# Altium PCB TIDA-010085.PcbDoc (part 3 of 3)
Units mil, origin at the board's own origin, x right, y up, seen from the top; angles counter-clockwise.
Board outline 1968.5 x 2559.06 mil, 4 copper layers (Top Layer, Signal Layer 1, Signal Layer 2, Bottom Layer), stack 5.6 mil thick; 254 components, 133 nets, 771 pads, 156 vias.
Unrouted connection lines stored in the file: 2.
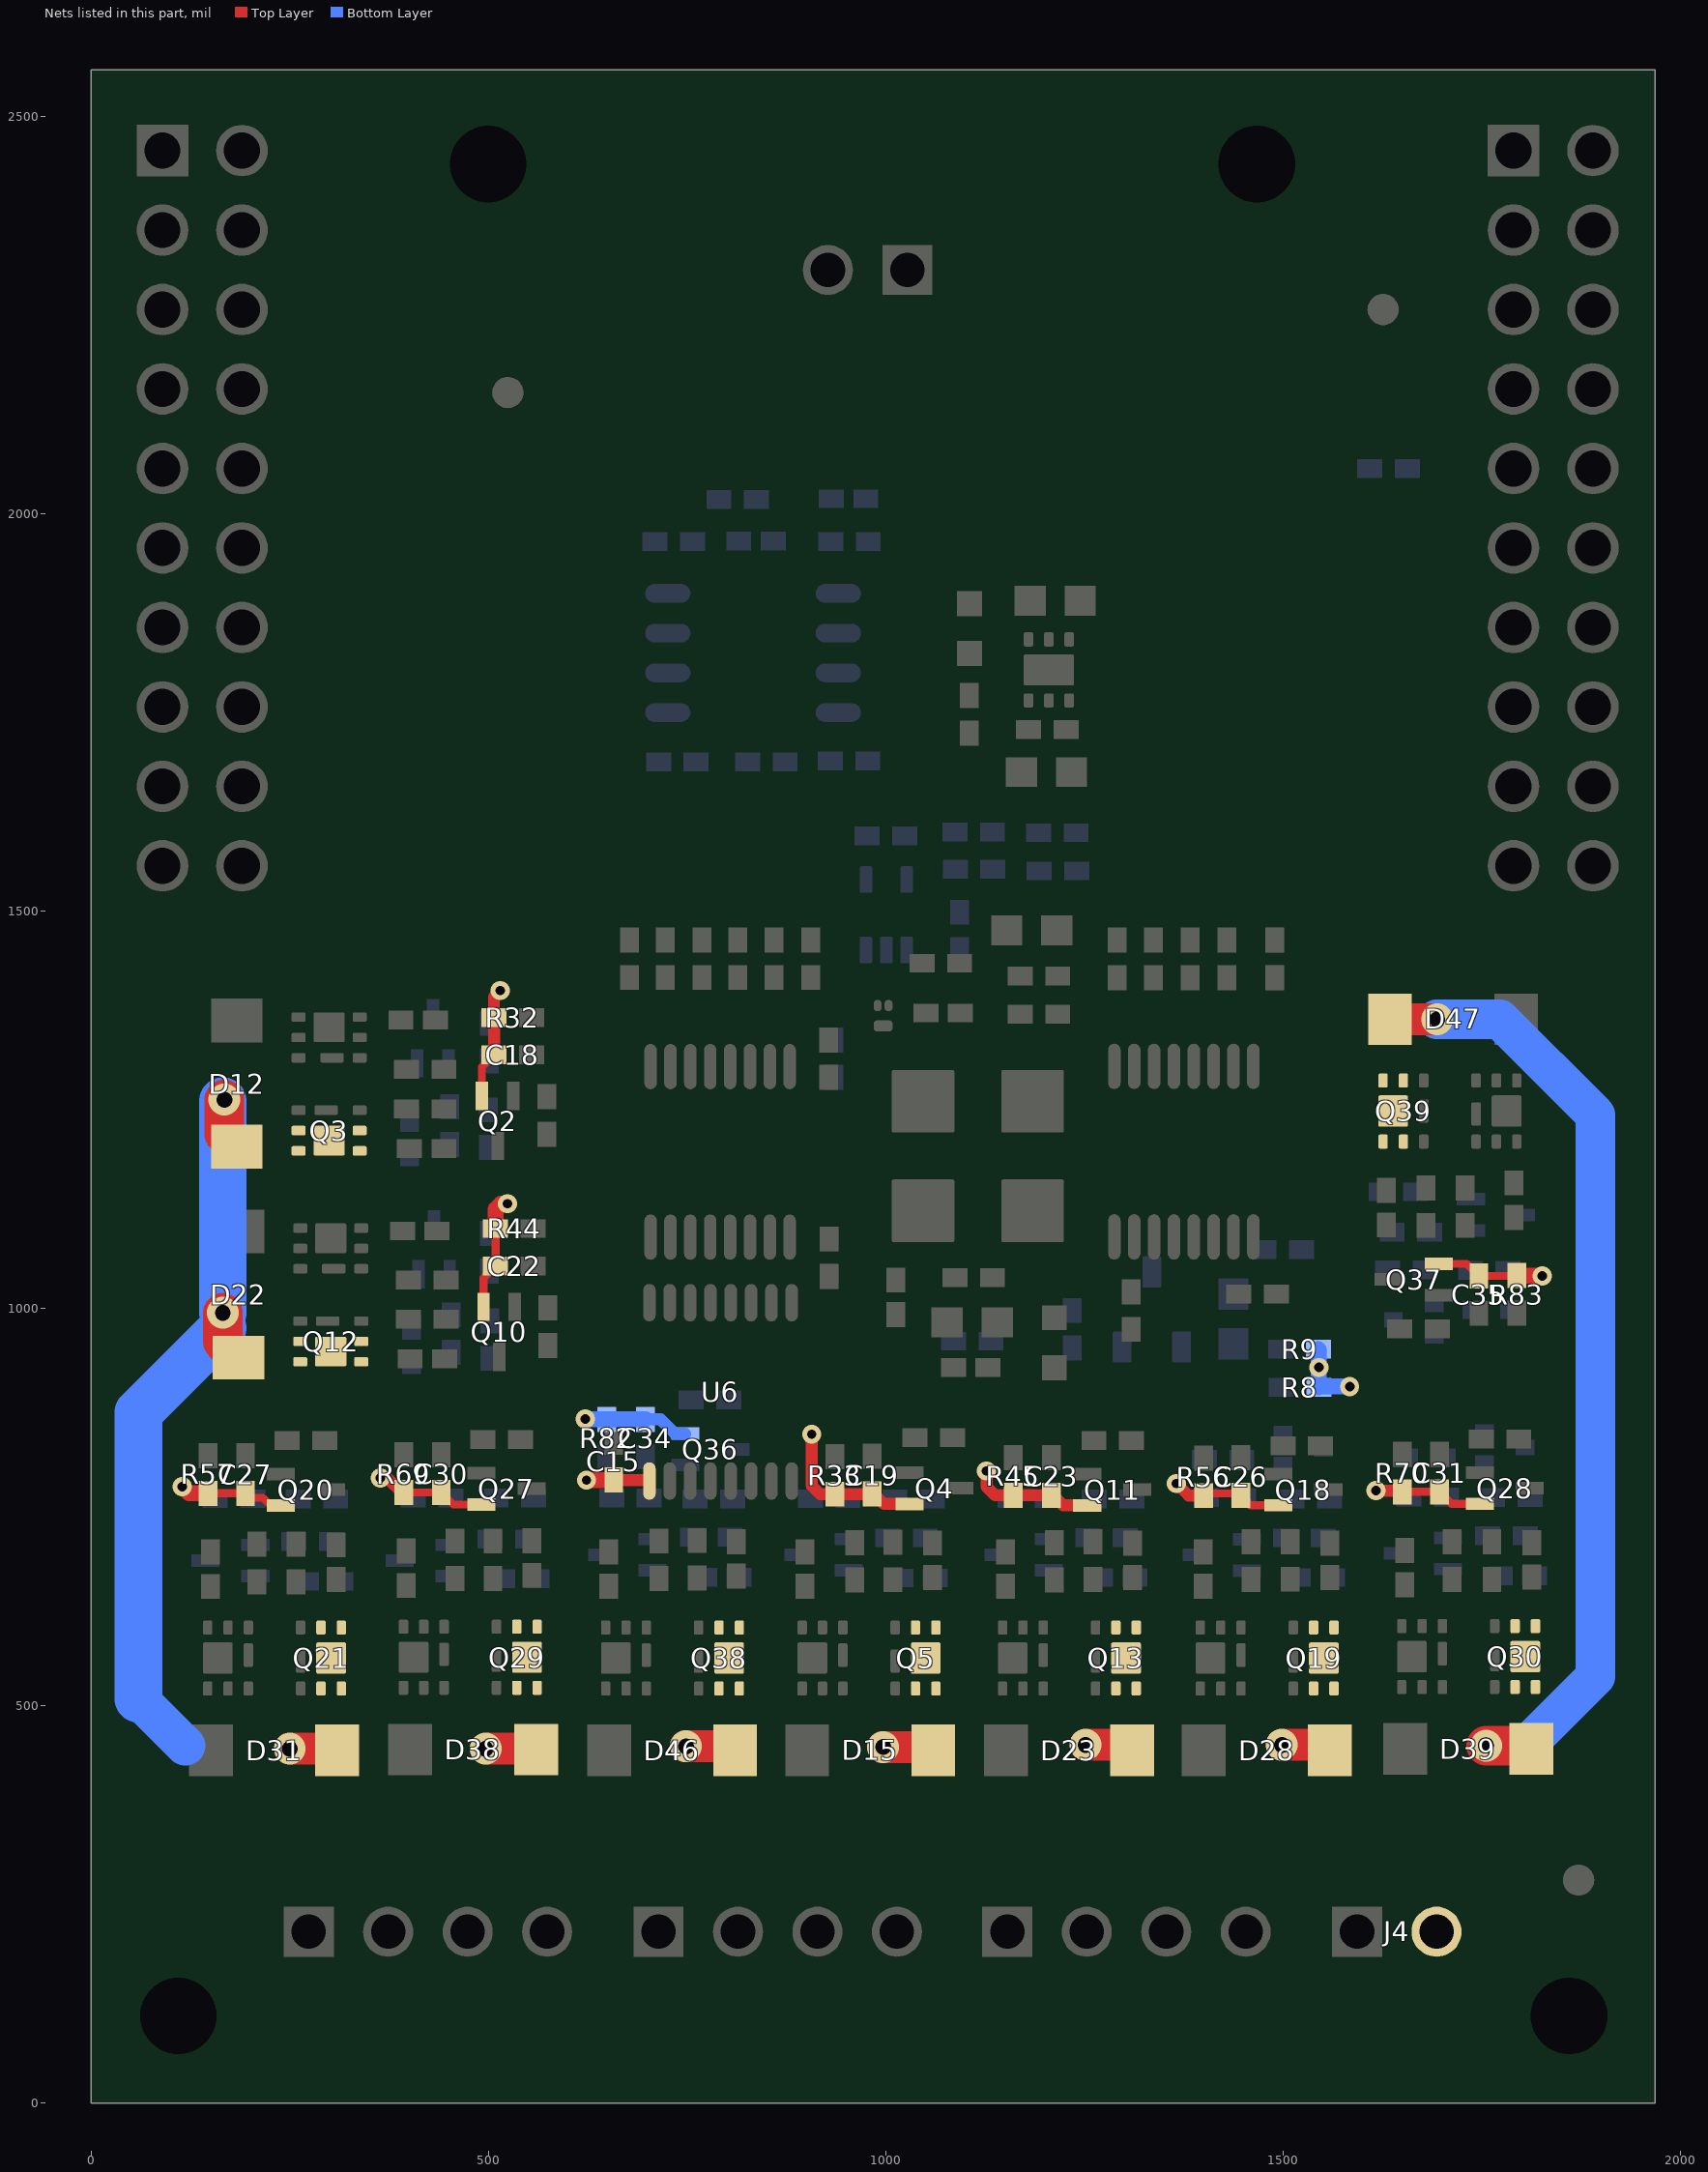
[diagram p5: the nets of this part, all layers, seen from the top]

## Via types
v1: diameter 24, hole 12, Top Layer to Bottom Layer, tented both sides, 144 vias
v2: diameter 40, hole 20, Top Layer to Bottom Layer, 10 vias
v3: diameter 19.68, hole 7.87, Top Layer to Bottom Layer, 2 vias

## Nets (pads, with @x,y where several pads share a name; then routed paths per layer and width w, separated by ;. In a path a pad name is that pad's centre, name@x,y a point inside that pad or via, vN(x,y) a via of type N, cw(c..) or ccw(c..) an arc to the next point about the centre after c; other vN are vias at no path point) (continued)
RC: D12.2 D15.2 D22.2 D23.2 D28.2 D31.2 D38.2 D39.2 D46.2 D47.2 J4.2 Q3.1 Q3.2 Q3.5 Q3.6 Q3.8 Q5.1 Q5.2 Q5.5 Q5.6 Q5.8 Q12.1 Q12.2 Q12.5 Q12.6 Q12.8 Q13.1 Q13.2 Q13.5 Q13.6 Q13.8 Q19.1 Q19.2 Q19.5 Q19.6 Q19.8 Q21.1 Q21.2 Q21.5 Q21.6 Q21.8 Q29.1 Q29.2 Q29.5 Q29.6 Q29.8 Q30.1 Q30.2 Q30.5 Q30.6 Q30.8 Q38.1 Q38.2 Q38.5 Q38.6 Q38.8 Q39.1 Q39.2 Q39.5 Q39.6 Q39.8 | length 2596.7
  Top Layer w40: v2(250.24,446.29) 307.91,446.29 D31.2@309.91,444.29 ; v2(496.7,446.29) D38.2@557.57,446.29 ; D38.2@553.57,446.29 555.42,444.44 D38.2@556.27,445.29 ; v2(748.76,449.29) 805.73,449.29 D46.2@810.73,444.29 D46.2@810.73,452.14 ; v2(996.84,448.29) 1053.98,448.29 D15.2@1057.98,444.29 ; v2(1251.56,451.12) 1303.26,451.12 D23.2@1310.09,444.29 ; v2(1498.56,451.12) 1552.15,451.12 D28.2@1558.98,444.29 ; D47.2@1631.57,1364.61 1631.95,1364.23 v2@1694,1364.23
  Top Layer w50: v2(166,994.68) 166,958.23 D22.2@185.83,938.4 D22.2@185.68,938.25 ; v2(168,1263) 168,1219.57 D12.2@183.78,1203.79 ; v2(1755.56,450.12) 1808.44,450.12 D39.2@1812.45,446.11
  Bottom Layer w50: 60,509 118.88,450.12 ; v2@166,975.57 v2(166,994.68) ; v2@166,1261 v2(168,1263) ; v2@1694,1364.23 1772.62,1364.23 1893,1243.85 1893,537 1806.12,450.12
  Bottom Layer w60: 60,509 60,869.57 v2@166,975.57 ; v2(166,994.68) v2@166,1261
  other v2: 1694,1364
VGD_ISO: C15.1 C18.1 C19.1 C22.1 C23.1 C26.1 C27.1 C30.1 C31.1 C34.1 C35.1 Q2.2 Q4.2 Q10.2 Q11.2 Q18.2 Q20.2 Q27.2 Q28.2 Q36.2 Q37.2 R8.2 R9.1 R32.2 R33.2 R44.2 R45.2 R56.2 R57.2 R69.2 R70.2 R82.2 R83.2 U6.9 | length 1641.5
  Top Layer w10: R57.2@147.58,767.67 193.82,767.67 199.49,762 216.23,762 225.63,752.6 Q20.2@245.08,752.6 ; R69.2@393.94,768.67 C30.1@440.94,768.67 456.01,753.6 Q27.2@491.45,753.6 ; Q2.2@492.1,1267.61 492.1,1304.06 C18.1@507.16,1319.12 ; Q10.2@494.14,1002.23 494.14,1038.67 C22.1@509.21,1053.73 R44.2@509.21,1100.73 ; R56.2@1400,767.35 1443.34,767.35 1443.65,767.67 1458.71,752.6 Q18.2@1494.15,752.6 ; R70.2@1650.11,769.49 C31.1@1697.11,769.49 1712.18,754.43 Q28.2@1747.62,754.43 ; Q37.2@1696.07,1056.29 1731.51,1056.29 C35.1@1746.57,1041.23 1793.85,1041.23 R83.2@1794.16,1041.54
  Top Layer w15: v1(364.31,787) 372.85,787 R69.2@392.56,767.29 ; R32.2@507.16,1366.12 507.16,1392.33 v1(515.13,1400.3) ; C18.1@507.52,1318.92 R32.2@507.52,1366.14 ; C15.1@658,784.38 701.46,784.38 U6.9@702.78,783.06 ; v1(907,842) 907,777.22 917.63,766.59 R33.2@936.33,766.59 979.12,766.59 979.67,766.05 981.99,766.05 C19.1@982.86,766.92 985.41,766.92 998.07,754.27 Q4.2@1029.97,754.27 ; v1(1127,795.67) 1127,776 1137.83,765.17 R45.2@1160.56,765.17 C23.1@1208.56,765.17 1210.88,765.17 1223.65,752.39 Q11.2@1253.68,752.39 ; v1(1366,780) 1381.32,764.68 R56.2@1400,764.68 ; v1(1617,771) 1648.6,771 R70.2@1650.11,769.49
  Top Layer w20: v1(115,776.11) 123.45,767.67 R57.2@147.58,767.67 ; R69.2@392.56,767.29 R69.2@393.94,768.67 ; R44.2@509.21,1100.73 509.21,1125.21 516.07,1132.07 v1(524.29,1132.07) ; v1(623.71,784.23) 657.39,784.23 657.62,784 C15.1@658,784.38 ; R83.2@1794.16,1041.54 1794.48,1041.23 v1(1826.12,1041.23)
  Bottom Layer w15: C34.1@698,860.62 717,860.62 734.94,842.69 Q36.2@748.06,842.69
  Bottom Layer w20: v1(622,861) 648.62,861 R82.2@649,860.62 C34.1@698,860.62 ; R9.1@1544.62,949 1545.15,948.47 R8.2@1545.15,901 1546.15,902 v1(1584,902)
  other v1: 1545.15,926
pads on no net: FID1.1 FID2.1 FID3.1 FID4.1 FID5.1 FID6.1 H1. H2. H3. H4. J2.2 J2.3 J2.5 J2.6 J2.7 J2.8 J2.10 J2.12 J2.14 J2.16 J2.18 J2.20 J3.1 J3.3 J3.4 J3.5 J3.6 J3.7 J3.8 J3.10 J3.11 J3.12 J3.13 J3.15 J3.17 J3.19 Q3.0 Q5.0 Q8.0 Q9.0 Q12.0 Q13.0 Q16.0 Q17.0 Q19.0 Q21.0 Q24.0 Q26.0 Q29.0 Q30.0 Q34.0 Q35.0 Q38.0 Q39.0 Q43.0 Q44.0 U1.7@1187.66,1803.68 U1.7@1223.09,1803.68 U2.1 U7.7

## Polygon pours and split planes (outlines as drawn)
GND on Top Layer "GND_L01_P116" (solid, remove dead copper, pour order 116): 22.26,2505.45 54.03,2534.64 1917.26,2534.64 1945.26,2506.64 1945.26,1498.71 1926.19,1479.64 1568.64,1479.64 1495,1406 1495,1307 1461,1273 1329,1273 1258,1344 1010.19,1344 929.19,1263 675.87,1263 653.1,1284.4 653.1,1421.21 599.66,1475.48 41.44,1476.56 22.26,1495.74
ISO_GND on Top Layer "ISO_GND_L01_P106" (solid, remove dead copper, pour order 106): 1119,919 1124,914 1145,914 1186,955 1278,955 1294,971 1294,1045 1294,1113.5 1289.5,1118 1180,1118 1119,1057
12V_ISO on Top Layer "12V_ISO_L01_P104" (solid, remove dead copper, pour order 104): 1000,990.55 1004.13,994.68 1050.44,994.68 1067,1011.24 1067,1048 1071,1052 1096.75,1052 1100,1048.75 1100,917 1096,913 1005,913 1000,918
NetC24_2 on Top Layer "NETC24_2_L01_P102" (solid, remove dead copper, pour order 102): 348.94,1053.69 346.83,1055.8 293.52,1055.8 290.81,1053.08 290.81,1040.77 254.83,1004.8 254.83,980.47 256.5,978.8 309.83,978.8 312.83,981.8 312.83,997.83 348.77,1033.77
NetC20_2 on Top Layer "NETC20_2_L01_P100" (solid, remove dead copper, pour order 100): 347.9,1318.3 344.9,1321.3 291.59,1321.3 289.9,1319.61 289.9,1307.3 252.9,1270.3 252.9,1245.97 254.57,1244.3 307.9,1244.3 310.9,1247.3 310.9,1265.41 347.76,1302.28
NetC37_2 on Top Layer "NETC37_2_L01_P098" (solid, remove dead copper, pour order 98): 1674.19,1295.78 1671,1292.59 1671,1236.91 1673.91,1234 1690.59,1234 1723,1201.59 1747.33,1201.59 1749,1203.26 1749,1256.59 1746,1259.59 1724,1259.59 1687.93,1295.66
NetC33_2 on Top Layer "NETC33_2_L01_P096" (solid, remove dead copper, pour order 96): 1769,515 1772,518 1772,571.31 1770.31,573 1758.61,573 1721.61,610 1696.67,610 1695,608.33 1695,555 1698,552 1720,552 1756.9,515.1
NetC28_2 on Top Layer "NETC28_2_L01_P094" (solid, remove dead copper, pour order 94): 1516,513 1519,516 1519,569.31 1517.31,571 1505,571 1468,608 1443.67,608 1442,606.33 1442,553 1445,550 1467,550 1503.9,513.1
NetC25_2 on Top Layer "NETC25_2_L01_P092" (solid, remove dead copper, pour order 92): 1267,513 1270,516 1270,569.31 1268.31,571 1256,571 1219,608 1194.67,608 1193,606.33 1193,553 1196,550 1218,550 1254.9,513.1
NetC21_2 on Top Layer "NETC21_2_L01_P090" (solid, remove dead copper, pour order 90): 1015,513.1 1018,516.1 1018,569.41 1016.31,571.1 1008.66,571.1 971.66,608.1 942.67,608.1 941,606.43 941,553.1 944,550.1 966,550.1 1002.9,513.2
NetC36_2 on Top Layer "NETC36_2_L01_P088" (solid, remove dead copper, pour order 88): 767,513.1 770,516.1 770,569.41 768.31,571.1 756,571.1 719,608.1 694.67,608.1 693,606.43 693,553.1 696,550.1 718,550.1 754.9,513.2
NetC32_2 on Top Layer "NETC32_2_L01_P086" (solid, remove dead copper, pour order 86): 513,514 516,517 516,570.31 514.31,572 502,572 465,609 440.67,609 439,607.33 439,554 442,551 464,551 500.9,514.1
NetC29_2 on Top Layer "NETC29_2_L01_P084" (solid, remove dead copper, pour order 84): 267,513 270,516 270,569.31 268.31,571 257,571 220,608 194.67,608 193,606.33 193,553 196,550 221.87,550 258.81,513.07
RC on Top Layer "RC_L01_P056" (solid, remove dead copper, pour order 56): 348.65,1228.57 348.65,1194.57 346.65,1192.57 233.65,1192.57 217.65,1176.57 152.65,1176.57 151.65,1177.57 151.65,1230.57 152.93,1231.85 345.65,1231.57
RC on Top Layer "RC_L01_P054" (solid, remove dead copper, pour order 54): 350.83,962.41 350.83,928.41 348.83,926.41 235.83,926.41 219.83,910.41 154.83,910.41 153.83,911.41 153.83,964.41 155.11,965.69 347.83,965.41
RC on Top Layer "RC_L01_P052" (solid, remove dead copper, pour order 52): 286.25,609.29 320.25,609.29 322.25,607.29 322.25,494.29 338.25,478.29 338.25,413.29 337.25,412.29 284.25,412.29 282.97,413.57 283.25,606.29
RC on Top Layer "RC_L01_P050" (solid, remove dead copper, pour order 50): 531.61,609.33 565.61,609.33 567.61,607.33 567.61,494.33 583.61,478.33 583.61,413.33 582.61,412.33 529.61,412.33 528.33,413.61 528.61,606.33
RC on Top Layer "RC_L01_P048" (solid, remove dead copper, pour order 48): 786.76,609.29 820.76,609.29 822.76,607.29 822.76,494.29 838.76,478.29 838.76,413.29 837.76,412.29 784.76,412.29 783.48,413.57 783.76,606.29
RC on Top Layer "RC_L01_P046" (solid, remove dead copper, pour order 46): 1034.32,608.29 1068.32,608.29 1070.32,606.29 1070.32,493.29 1086.32,477.29 1086.32,412.29 1085.32,411.29 1032.32,411.29 1031.04,412.57 1031.32,605.29
RC on Top Layer "RC_L01_P044" (solid, remove dead copper, pour order 44): 1285.76,608.29 1319.76,608.29 1321.76,606.29 1321.76,493.29 1337.76,477.29 1337.76,412.29 1336.76,411.29 1283.76,411.29 1282.48,412.57 1282.76,605.29
RC on Top Layer "RC_L01_P042" (solid, remove dead copper, pour order 42): 1534.65,609.29 1568.65,609.29 1570.65,607.29 1570.65,494.29 1586.65,478.29 1586.65,413.29 1585.65,412.29 1532.65,412.29 1531.37,413.57 1531.65,606.29
RC on Top Layer "RC_L01_P040" (solid, remove dead copper, pour order 40): 1789.11,611.11 1823.11,611.11 1825.11,609.11 1825.11,496.11 1841.11,480.11 1841.11,415.11 1840.11,414.11 1787.11,414.11 1785.84,415.39 1786.11,608.11
RC on Top Layer "RC_L01_P038" (solid, remove dead copper, pour order 38): 1655.57,1200.61 1621.57,1200.61 1619.57,1202.61 1619.57,1315.61 1603.57,1331.61 1603.57,1396.61 1604.57,1397.61 1657.57,1397.61 1658.85,1396.33 1658.57,1203.61
COIL-10 on Top Layer "COIL-10_L01_P036" (solid, remove dead copper, pour order 36): 1798.57,1200.61 1763.57,1200.61 1761.57,1202.61 1761.57,1397.61 1764.57,1400.61 1816.57,1400.61 1818.57,1398.61 1818.57,1329.61 1801.57,1312.61 1801.57,1203.61
COIL-9 on Top Layer "COIL-9_L01_P034" (solid, remove dead copper, pour order 34): 1645.11,610.11 1680.11,610.11 1682.11,608.11 1682.11,413.11 1679.11,410.11 1627.11,410.11 1625.11,412.11 1625.11,481.11 1642.11,498.11 1642.11,607.11
COIL-8 on Top Layer "COIL-8_L01_P032" (solid, remove dead copper, pour order 32): 1391.65,608.29 1426.65,608.29 1428.65,606.29 1428.65,411.29 1425.65,408.29 1373.65,408.29 1371.65,410.29 1371.65,479.29 1388.65,496.29 1388.65,605.29
COIL-7 on Top Layer "COIL-7_L01_P030" (solid, remove dead copper, pour order 30): 1142.76,608.29 1177.76,608.29 1179.76,606.29 1179.76,411.29 1176.76,408.29 1124.76,408.29 1122.76,410.29 1122.76,479.29 1139.76,496.29 1139.76,605.29
COIL-6 on Top Layer "COIL-6_L01_P028" (solid, remove dead copper, pour order 28): 890.32,608.29 925.32,608.29 927.32,606.29 927.32,411.29 924.32,408.29 872.32,408.29 870.32,410.29 870.32,479.29 887.32,496.29 887.32,605.29
COIL-5 on Top Layer "COIL-5_L01_P026" (solid, remove dead copper, pour order 26): 643.76,608.29 678.76,608.29 680.76,606.29 680.76,411.29 677.76,408.29 625.76,408.29 623.76,410.29 623.76,479.29 640.76,496.29 640.76,605.29
COIL-4 on Top Layer "COIL-4_L01_P024" (solid, remove dead copper, pour order 24): 388.61,609.29 423.61,609.29 425.61,607.29 425.61,412.29 422.61,409.29 370.61,409.29 368.61,411.29 368.61,480.29 385.61,497.29 385.61,606.29
COIL-3 on Top Layer "COIL-3_L01_P022" (solid, remove dead copper, pour order 22): 142.25,608.29 177.25,608.29 179.25,606.29 179.25,411.29 176.25,408.29 124.25,408.29 122.25,410.29 122.25,479.29 139.25,496.29 139.25,605.29
COIL-2 on Top Layer "COIL-2_L01_P020" (solid, remove dead copper, pour order 20): 349.83,1106.41 349.83,1071.41 347.83,1069.41 152.83,1069.41 149.83,1072.41 149.83,1124.41 151.83,1126.41 220.83,1126.41 237.83,1109.41 346.83,1109.41
no net on Top Layer "NONET_L01_P018" (solid, remove dead copper, pour order 18): 382.78,1374.51
COIL-1 on Top Layer "COIL-1_L01_P016" (solid, remove dead copper, pour order 16): 348.86,1372.3 348.86,1337.3 346.86,1335.3 151.85,1335.3 148.86,1338.3 148.86,1390.3 150.86,1392.3 219.86,1392.3 236.86,1375.3 345.86,1375.3
GND on Top Layer "GND_L01_P010" (solid, remove dead copper, pour order 10): 1251.38,1726.68 1242.38,1717.68 1222.38,1717.68 1211.38,1728.68 1211.38,1750.68 1195.38,1766.68 1195.38,1786.68 1204.38,1795.68 1236.72,1795.68 1251.38,1781.02
GND on Bottom Layer "GND_L04_P110" (solid, remove dead copper, pour order 110): 22.26,2505.45 54.03,2534.64 1917.26,2534.64 1945.26,2506.64 1945.26,1498.71 1926.19,1479.64 1596.19,1479.64 1558,1441.45 1558,1370 1461,1273 1274,1273 1225,1322 1021,1322 962,1263 675.87,1263 653.1,1284.4 653.1,1421.21 599.66,1475.48 41.44,1476.56 22.26,1495.74
RC on Bottom Layer "RC_L04_P060" (solid, remove dead copper, pour order 60): 52.04,541 62,541 128,475 1796,475 1869,548 1903,548 1918,533 1918,456 1727,265 1727,202 1708,183 1679.3,183 1660,202.3 1660,270 1555,375 110,375 25,460 25,506.43
GND on Signal Layer 1 "GND_L02_P114" (solid, remove dead copper, pour order 114): 22.26,2505.45 54.03,2534.64 1917.26,2534.64 1945.26,2506.64 1945.26,1498.71 1926.19,1479.64 1596.19,1479.64 1558,1441.45 1558,1370 1461,1273 1274,1273 1225,1322 1021,1322 962,1263 675.87,1263 653.1,1284.4 653.1,1421.21 599.66,1475.48 41.44,1476.56 22.26,1495.74
ISO_GND on Signal Layer 1 "ISO_GND_L02_P108" (solid, remove dead copper, pour order 108): 163.33,516.44 1800.44,516.44 1868,584 1868,1285 1845,1308 1702.77,1308 1606,1211.23 1606,1160 1579,1133 592,1133 560,1165 560,1381 538.61,1402.39 269.39,1402.39 241,1374 241,931.58 107,797.58 107,556.11
3V3 on Signal Layer 2 "3V3_L03_P082" (solid, remove dead copper, pour order 82): 31,2501 64,2534 296,2534 948,1882 1469.68,1882 1551.33,1800.35 1551.33,1489.33 1478,1416 675.61,1416 589.91,1501.7 589.91,1747.09 31,2306
VGD_ISO on Signal Layer 2 "VGD_ISO_L03_P078" (solid, remove dead copper, pour order 78): 372.66,1414 538,1414 597,1355 597,1147 597,1093.96 633.96,1057 1511,1057 1586.07,1132.07 1840.93,1132.07 1870,1103 1870,757.67 1816.33,704 114,704 87,731 87,882 106,901 221,901 354,1034 354,1395.34

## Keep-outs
Keep-Out Layer:
  circle w8: c1466,2441 r125
  circle w8: c500,2441 r125
  lines w6: 15,15 15,2544.05 1953.5,2544.05 1953.5,15 15,15
  text ".Layer_Name" at -885.15,-1620.64 h60

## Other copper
Top Layer:
  text ".layer_Name" at -870.15,-1610.15 h60
Signal Layer 1:
  region: 1822,261.58 1822,300.58 1847.65,326.24 1895.76,326.24 1918,304 1918,254.13 1899.47,235.6 1847.98,235.6
  text "'.Layer_Name'" at -955,-1637 h60
Signal Layer 2:
  region: 1575.98,2237.76 1575.98,2276.76 1601.64,2302.41 1649.75,2302.41 1671.98,2280.17 1671.98,2230.3 1653.45,2211.77 1601.97,2211.77
  region: 1822,261.58 1822,300.58 1847.65,326.24 1895.76,326.24 1918,304 1918,254.13 1899.47,235.6 1847.98,235.6
  text "'.Layer_Name'" at -955,-1637 h60
Bottom Layer:
  region: 90.08,2457.17
  text ".Layer_Name" at -811.15,-1620.15 h60

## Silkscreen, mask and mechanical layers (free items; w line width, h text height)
Top Overlay:
  lines w10: 121,1785.9 142,1806.9 261,1806.9 ; 121,1885.9 142,1906.9 261,1906.9 ; 121.4,1989.3 139,2006.9 258,2006.9 ; 122.4,1588.3 141,1606.9 260,1606.9 ; 122.4,1688.3 141,1706.9 260,1706.9 ; 122.85,2087.85 140,2105 259,2105 ; 133.11,2503.11 143,2513 146,2513 148,2513 233,2513 239,2513 ; 1716,2059 1743,2059 ; 1717,1603.9 1836,1603.9 1838.1,1603.9 1851.5,1590.5 ; 1718,1707.9 1837,1707.9 ; 1718,1905.9 1837,1905.9 ; 1721,1808.9 1840,1808.9 ; 1727.42,2503.73 1846.42,2503.73 ; 1839.1,1707.9 1849.99,1697.01 ; 1839.1,1905.9 1855,1890 ; 1842.1,1808.9 1858.5,1792.5 ; 1848.52,2503.73 1860.12,2492.12
  text "3V3" at 246,2488 h30
  text "GND" at 1602.99,2472.53 h30
  text "5V" at 1031,2460 h30
  text "GND" at 861,2455 h30
  text "GND" at 239,2309 h30
  text "IN6" at 260,2079.2 h30
  text "PWM" at 1580,2034.32 h30
  text "IN5" at 260,1987 h30
  text "IN7" at 1601,1891.2 h30
  text "IN4" at 260,1884 h30
  text "IN8" at 1580,1793 h30
  text "IN3" at 260,1786 h30
  text "IN9" at 1580,1690 h30
  text "IN2" at 260,1687 h30
  text "IN10" at 1580,1592 h30
  text "IN1" at 260,1586 h30
  text "C" at 263,32 h30
  text "S1" at 352,32 h30
  text "S2" at 449,32 h30
  text "S3" at 552,32 h30
  text "C" at 720,32 h30
  text "S4" at 790,32 h30
  text "S5" at 894,32 h30
  text "S6" at 1000,32 h30
  text "S7" at 1158.86,32 h30
  text "S8" at 1237,32 h30
  text "S9" at 1342,32 h30
  text "S10" at 1425.64,32 h30
  text "C" at 1571.29,32 h30
  text "RC" at 1692,32 h30
  text ".layer_Name" at -844.15,-1608.15 h60
Bottom Overlay:
  lines w6: 1586,539 1610,563 1610,609.27 1593.27,626 ; 1593.27,626 1593.27,626 ; 1593.27,626 1593.27,609.63 1609.64,626 1593.27,626
  text "24-VAC Multi-channel Solid State Relay" at 1537,2209 h72.83
  text "For evaluation only; not FCC approved for resale." at 1684,310 h72.83
  text ".Layer_Name" at -885.15,-1620.64 h60
Top Paste:
  text ".Layer_Name" at -897.15,-1623.64 h60
Bottom Paste:
  text ".Layer_Name" at -897.15,-1623.64 h60
Top Solder:
  text ".Layer_Name" at -869.15,-1631.15 h60
Bottom Solder:
  text ".Layer_Name" at -822.15,-1627.15 h60
M1 Board Outline:
  the board outline again, w6
  text "'.Layer_Name'" at -927.15,-1620.15 h60
M2 Board Dimensions:
  rectangle: -867.65,-767.15 -492.65,-642.15
  rectangle: -992.65,-642.15 -867.65,-517.15
  lines w7: -992.65,-642.15 7.35,-642.15 ; -867.65,-767.15 -867.65,-517.15 ; -742.65,-767.15 -742.65,-517.15 ; -492.65,-767.15 -492.65,-517.15 ; -242.65,-767.15 -242.65,-517.15 ; -992.65,-767.15 -992.65,-517.15 7.35,-517.15 7.35,-767.15 -992.65,-767.15
  lines w10: -992.65,-832.15 -992.65,-812.15 ; -932.65,-842.15 -992.65,-822.15 ; -932.65,-802.15 -992.65,-822.15 ; -768.57,-822.15 -992.65,-822.15 ; -216.73,-822.15 7.35,-822.15 ; -52.65,-842.15 7.35,-822.15 ; -52.65,-802.15 7.35,-822.15 ; 7.35,-832.15 7.35,-812.15
  text "1000 (mil)" at -758.57,-858.14 h60
M3 3D STEP Top:
  text ".Layer_Name" at -885.15,-1620.64 h60
M4 3D STEP Bottom:
  text ".Layer_Name" at -885.15,-1620.64 h60
M5 Assembly Top:
  lines w8: -1754.15,-1692.32 4845.85,-1692.32 ; -1754.15,-1488.98 4847.85,-1488.98 ; -1754.15,-1285.65 -1754.15,-1895.65 2250.85,-1895.65 4847.85,-1895.65 4847.85,-1285.65 -1753.65,-1285.65 -1753.65,-1895.65 ; 710.85,-1895.65 710.85,-1285.65 ; 1977.85,-1488.98 1977.85,-1285.65 ; 2817.85,-1488.98 2817.85,-1285.65 ; 3439.85,-1902.15 3439.85,-1699.32
  text "COMPONENTS MARKED 'DNP' SHOULD NOT BE POPULATED." at -308.65,-1080.65 h60
  text "ASSEMBLY VARIANT:" at -309.15,-1196.15 h60
  text ".VariantName" at 726.85,-1196.15 h60
  text "ALL ARTWORK VIEWED FROM TOP SIDE" at -1690.65,-1417.82 h60
  text "BOARD #:" at 785.85,-1417.82 h60
  text ".PRJ_Number" at 1331.35,-1417.82 h60
  text "REV:" at 2175.85,-1417.82 h60
  text ".PCB_Rev" at 2467.35,-1417.82 h60
  text "SVN REV:" at 3013.85,-1417.82 h60
  text ".VersionControl_RevNumber" at 3519.85,-1417.82 h60
  text ".layer_Name" at -927.15,-1600.15 h60
  text "LAYER NAME =" at -1697.15,-1607.15 h60
  text ".TID" at 1181,-1617 h60
  text "TID #:" at 774.85,-1623.82 h60
  text ".plot_File_Name" at -932.15,-1805.15 h60
  text "PLOT NAME =" at -1691.15,-1826.49 h60
  text "GENERATED    :" at 787.85,-1826.49 h60
  text ".Print_Date" at 1657.35,-1826.49 h60
  text ".Print_Time" at 2386.35,-1826.49 h60
  text "TEXAS INSTRUMENTS" at 3650.85,-1826.49 h60
M6 Assembly Bottom:
  circle w6: c21,2457 r10
  circle w6: c1684.37,2457.17 r17.64
  lines w6: -1754.65,-1489.48 4847.35,-1489.48 ; -1752.65,-1692.82 4847.35,-1692.82 ; 275.35,-1489.48 275.35,-1286.15 ; 1115.35,-1489.48 1115.35,-1286.15 ; 2382.35,-1896.15 2382.35,-1286.15 ; 3271.35,-1896.15 4846.85,-1896.15 4846.85,-1286.15 -1754.65,-1286.15 -1754.65,-1896.15 842.35,-1896.15 4847.35,-1896.15 4847.35,-1286.15
  lines w8: -347.65,-1902.65 -347.65,-1699.82
  text "COMPONENTS MARKED 'DNP' SHOULD NOT BE POPULATED." at 4639.85,-1080.15 h60
  text ".VariantName" at 3595.85,-1196.15 h60
  text "ASSEMBLY VARIANT:" at 4634.85,-1196.15 h60
  text "SVN REV:" at 79.35,-1418.32 h60
  text ".PCB_Rev" at 625.85,-1418.32 h60
  text "REV:" at 917.35,-1418.32 h60
  text ".PRJ_Number" at 1761.85,-1418.32 h60
  text "BOARD #:" at 2307.35,-1418.32 h60
  text "PCB VIEWED FROM BOTTOM SIDE" at 4783.85,-1418.32 h60
  text ".VersionControl_RevNumber" at -469.15,-1418.82 h60
  text ".TID" at 1908,-1601 h60
  text "LAYER NAME =" at 4778.85,-1603.15 h60
  text "TID #:" at 2314.15,-1607.82 h60
  text ".Layer_Name" at 4005.85,-1610.15 h60
  text "TEXAS INSTRUMENTS" at -558.65,-1826.99 h60
  text ".Print_Time" at 706.85,-1826.99 h60
  text ".Print_Date" at 1435.85,-1826.99 h60
  text "GENERATED    :" at 2305.35,-1826.99 h60
  text ".plot_File_Name" at 3978.35,-1826.99 h60
  text "PLOT NAME =" at 4783.85,-1826.99 h60
M9 Title Sheet:
  drawing of 57 lines, arcs and shapes, not listed
  text "1" at -722.31,7274.35 h70
  text "2" at 1773.35,7274.35 h70
  text "3" at 4262.69,7274.35 h70
  text "4" at 6769.36,7274.35 h70
  text "5" at 9268.35,7274.35 h70
  text "6" at 11773.35,7274.35 h70
  text "A" at -1878.65,6131.35 h70
  text "A" at 12921.35,6131.35 h70
  text "B" at -1878.65,3751.35 h70
  text "B" at 12921.35,3751.35 h70
  text "C" at -1878.65,1376.35 h70
  text "C" at 12921.35,1376.35 h70
  text "PROJECT TITLE:" at 9881.35,-484.65 h45
  text ".PRJ_Title" at 10033.85,-619.15 h50
  text "DESIGNED FOR:" at 9881.35,-785.65 h45
  text ".PRJ_Customer" at 9931.35,-925.65 h70
  text "D" at -1878.65,-993.65 h70
  text "D" at 12921.35,-993.65 h70
  text "FILE NAME:" at 9881.35,-1085.65 h45
  text ".PCB_File_Name_No_Path" at 9931.35,-1205.65 h70
  text "Texas Instruments (TI) and/or its licensors do not warrant the accuracy or completeness of this specification" at 4911.85,-1367.49 h45
  text "ENGINEER:" at 9881.35,-1375.65 h45
  text "LAYOUT BY:" at 11386.35,-1375.65 h45
  text "or any information contained therein. TI and/or its licensors do not warrant that this design will meet" at 4866.86,-1480.15 h45
  text ".PRJ_Engineer" at 9931.35,-1530.64 h70
  text ".PCB_Layout" at 11436.85,-1530.64 h70
  text "the specifications, will be suitable for your application or fit for any particular purpose, or will operate in" at 4866.86,-1592.82 h45
  text "ALTIUM DESIGNER VERSION:" at 11386.35,-1685.65 h45
  text "an implementation. TI and/or its licensors do not warrant that the design is production worthy. You should" at 4866.86,-1705.48 h45
  text "completely validate and test your design implementation to confirm the system functionality for your application." at 4911.85,-1818.15 h45
  text ".print_Scale" at 9931.35,-1818.98 h70
  text ".Application_BuildNumber" at 11436.85,-1818.98 h70
  text "2" at 1773.35,-2025.65 h70
  text "3" at 4262.69,-2025.65 h70
  text "4" at 6769.36,-2025.65 h70
  text "5" at 9268.35,-2025.65 h70
  text "6" at 11773.35,-2025.65 h70
M10 Fab Notes:
  drawing of 228 lines, arcs and shapes, not listed
  text "DESIGN INFORMATION" at 10918.87,6047.85 h60
  text "(REFER ALSO ARRAY/PANEL PROFILING INFORMATION)" at 10557.31,5886.14 h60
  text "BOARD SIZE" at 9871.31,5881.85 h60
  text "50mm" at 10333.63,5754.03 h60
  text "X" at 10839.31,5754.03 h60
  text "65mm" at 11070.63,5754.03 h60
  text "Number of Layers :" at 10274.31,5556.85 h60
  text "4" at 11369.12,5546.85 h60
  text "MIN. TRACK WIDTH:" at 10274.31,5417.85 h60
  text "10" at 11370.55,5417.85 h60
  text "MIL" at 11525.31,5417.85 h60
  text "MIN. CLEARANCE:" at 10274.31,5285.85 h60
  text "MIL" at 11525.31,5285.85 h60
  text "3.9" at 11330.85,5282.85 h60
  text "MIN. VIA PAD SIZE:" at 10274.31,5153.85 h60
  text "MIL" at 11635,5153 h60
  text "19.685" at 11270.85,5150.85 h60
  text "5.91 MIL" at 10969.31,5012.14 h60
  text "MINIMUM ANNULAR RING" at 9945.08,5007.86 h60
  text "EXTERNAL" at 11677.31,5007.86 h60
  text "PER" at 10145.08,4889.85 h60
  text "IPC-D-275 CLASS 2 LEVEL C" at 10365.08,4889.85 h60
  text "MIL, HOLES" at 11853.31,4777.56 h60
  text "+/-" at 11460.85,4776.85 h60
  text "+/-" at 12314.85,4776.85 h60
  text "REGISTRATION TOLERANCES:" at 9945.08,4771.85 h60
  text "METAL" at 11144.85,4771.85 h60
  text "5" at 11721.05,4771.85 h60
  text "3" at 12554.05,4771.85 h60
  text "MIL" at 12670.31,4771.85 h60
  text "MATERIAL:" at 9870.31,4562.39 h60
  text "FR-4 High Tg" at 10856.75,4422.06 h60
  text "X" at 10696.85,4414.85 h60
  text "FR-408" at 10291.31,4413.49 h60
  text "OTHER" at 11779.31,4413.49 h60
  text "63 MIL (1.6mm) +/-10%" at 10611.41,4250.77 h60
  text "THICKNESS:" at 9945.08,4246.49 h60
  text "X" at 10483.25,4246.49 h60
  text "OTHER" at 11896.31,4246.49 h60
  text "TOLERANCE:" at 9945.08,4088.49 h60
  text "X" at 10784.38,4088.49 h60
  text "ANSI IPC-6012 TYPE 3 CLASS 2" at 10971.33,4088.49 h60
  text "OTHER +/-" at 10971.31,3932.49 h60
  text "BOW & TWIST:" at 9945.08,3775.49 h60
  text "X" at 10784.38,3775.49 h60
  text "ANSI IPC-6012 TYPE 3 CLASS 2" at 10971.33,3775.49 h60
  text "OTHER +/-" at 10971.31,3616.98 h60
  text "COPPER THICKNESS:" at 3301.71,3548.2 h50
  text "COPPER THICKNESS (FINISHED):" at 9870.31,3481.49 h60
  text "1 OZ COPPER FOR ALL LAYERS" at 3306.71,3453.2 h50
  text "SELECTION OF CORE AND PREPEG THICKNESS IS UPTO FAB HOUSE." at 3306.71,3346.2 h50
  text "X" at 10618,3331 h60
  text "1.4MIL (1oz)" at 10750.31,3328.77 h60
  text "2MIL (1.4oz)" at 11517.31,3328.77 h60
  text "2.8MIL (2oz)" at 12244.31,3328.77 h60
  text "OUTER:" at 10227.31,3324.49 h60
  text "FINISHED  BOARD THICKNESS_1.6MM+/-10%" at 3294.62,3215 h50
  text "X" at 10618,3174 h60
  text "1.4MIL (1oz)" at 10750.31,3171.77 h60
  text "2.8MIL (2oz)" at 11517.31,3171.77 h60
  text "N/A" at 12243.85,3172.14 h60
  text "INNER SIGNAL:" at 9938.23,3167.49 h60
  text "DRILLING:" at 9870.31,3028.49 h60
  text "REFERENCE:" at 9945.08,2911.49 h60
  text "X" at 10593.31,2911.49 h60
  text "AS SHOWN" at 10780.31,2911.49 h60
  text "X" at 11494.31,2911.49 h60
  text "NC_DRILL FILES" at 11631.31,2911.49 h60
  text "PTH MIN COPPER THICKNESS:" at 9945.08,2753.49 h60
  text "X" at 11295.31,2753.49 h60
  text "1MIL" at 11432.31,2753.49 h60
  text "OTHER" at 11929.31,2753.49 h60
  text "BOARD FINISH:" at 9870.31,2594.49 h60
  text "SILKSCREEN:" at 10025.53,2476.49 h60
  text "X" at 10974.31,2476.49 h60
  text "TOP" at 11100.31,2476.49 h60
  text "X" at 11484.31,2476.49 h60
  text "BOTTOM" at 11611.31,2476.49 h60
  text "SILKSCREEN COLOR:" at 10025.53,2309.49 h60
  text "X" at 10973.27,2309.49 h60
  text "WHITE" at 11100.31,2309.49 h60
  text "OTHER" at 11611.31,2309.49 h60
  text "SOLDER RESIST COLOR:" at 10025.53,2139.49 h60
  text "X" at 10593.27,1980.29 h60
  text "GREEN" at 10720.31,1980.29 h60
  text "BLUE" at 11311.31,1980.29 h60
  text "OTHER" at 11849.31,1980.29 h60
  text "IMMERSION GOLD (ENIG)" at 10931.31,1791.77 h60
  text "ENEPIG" at 12268.85,1788.49 h60
  text "SURFACE FINISH:" at 9870.31,1787.49 h60
  text "X" at 10744.36,1787.49 h60
  text "IMM. TIN/SILVER OR EQUIV" at 10199.85,1630.49 h60
  text "OTHER" at 11631.31,1630.49 h60
  text "ARRAY/PANEL:" at 9870.31,1451.49 h60
  text "X" at 10744.31,1451.49 h60
  text "CUT AND TRIM PER MECH LAYER 1" at 10931.31,1447.2 h60
  text "N.C. ROUTE" at 10931.31,1295.49 h60
  text "V. SCORE" at 11797.31,1295.49 h60
  text "CERTIFICATION:" at 9870.31,1158.49 h60
  text "MATERIALS AND WORKMANSHIP FOR ALL PCBS" at 10595.31,1158.49 h60
  text "TO MEET OR EXCEED THE REQUIREMENTS OF:" at 10595.31,1060.49 h60
  text "X" at 10221.81,923.99 h60
  text "ANSI IPC-A-600F CLASS ->" at 10360.81,923.99 h60
  text "X" at 11999.87,923.99 h60
  text "2" at 12118.81,923.99 h60
  text "1" at 11803.81,922.49 h60
  text "3" at 12472.81,922.49 h60
  text "X" at 10223.87,764.49 h60
  text "UL 94V-0" at 10360.81,764.49 h60
  text "X" at 11035.87,764.49 h60
  text "RoHS" at 11172.81,764.49 h60
  text "OTHER" at 11817.21,764.49 h60
  text "PER ORDER" at 12214.27,764.49 h60
  text "FAB NOTE:" at 3430,745.47 h50
  text "VIA TENTING:" at 11087.85,630.85 h60
  text "X" at 11846.31,626.49 h60
  text "ADDITIONAL REQUIREMENTS:" at 9870.31,623.49 h60
  text "YES" at 11637.52,621.77 h60
  text "1)THIS IS NOT AN IMPEDANCE CONTROLLED BOARD" at 3446.65,617.27 h50
  text "NO" at 12002.32,616.54 h60
  text "MICROSECTION:" at 9945.08,508.49 h60
  text "YES" at 10850.81,508.49 h60
  text "2)ALL VIAS ARE NON TENTED OTHER THAN 12 MIL VIAS." at 3446.65,507.69 h50
  text "IMPEDANCE CONTROL:" at 11109.85,501.85 h60
  text "YES" at 12093.85,500.85 h60
  text "X" at 12635.85,493.85 h60
  text "NO" at 12469.32,483.54 h60
  text "3)IF NEED COPPER THIEVING CAN BE ADDED BASED ON COPPER BALANCING CALCULATION" at 3446.65,398.27 h50
  text "REQUIRED" at 11712.31,352.35 h60
  text "BARE BOARD ELEC. TEST:" at 9945.08,349.49 h60
  text "NONE" at 11250.81,349.49 h60
  text "X" at 11585.31,349.49 h60
  text "PER ORDER" at 12304.31,349.49 h60
  text "AND MAINTAIN 100MIL SPACING FROM ANY FUNCTIONAL CONDUCTOR." at 3534.65,282.69 h50
  text "MANUFACTURER'S UL:" at 9945.08,192.49 h60
  text "RAIL" at 11110.81,188.2 h60
  text "METAL" at 11602.62,188.2 h60
  text "X" at 11977.85,187.85 h60
  text "SILK" at 12114.31,188.2 h60
  text "4)VENDOR MAY ADJUST SOLDERMASK WHEREVER SOLDERMASK PADS ARE SAME SIZE(1:1)" at 3446.65,176.69 h50
  text "AS PER MANUFACTURING CAPABILITIES AND ALL OTHER SOLDERMASK PADS SHALL NOT BE MODIFIED" at 3534.65,63.69 h50
  text "PROVIDED NO ADJACENT COPPER IS EXPOSED AND NO CONFLICT PRODUCED WITH ANY STATED" at 3534.65,-37.31 h50
  text "\"VIA TENTING/COVERING\" REQUIREMENTS." at 3534.65,-130.31 h50
M11 Gerber Information:
  lines w8: -1754.15,-1692.32 4845.85,-1692.32 ; -1754.15,-1488.98 4847.85,-1488.98 ; -1754.15,-1285.65 -1754.15,-1895.65 2250.85,-1895.65 4847.85,-1895.65 4847.85,-1285.65 -1753.65,-1285.65 -1753.65,-1895.65 ; 710.85,-1895.65 710.85,-1285.65 ; 1977.85,-1488.98 1977.85,-1285.65 ; 2817.85,-1488.98 2817.85,-1285.65 ; 3439.85,-1902.15 3439.85,-1699.32
  text "BOARD #:" at 785.85,-1417.82 h60
  text ".PRJ_Number" at 1331.35,-1417.82 h60
  text "REV:" at 2175.85,-1417.82 h60
  text ".PCB_Rev" at 2467.35,-1417.82 h60
  text "SVN REV:" at 3013.85,-1417.82 h60
  text ".VersionControl_RevNumber" at 3519.85,-1417.82 h60
  text "ALL ARTWORK VIEWED FROM TOP SIDE" at -1691.65,-1423.82 h60
  text "LAYER NAME =" at -1693.15,-1607.15 h60
  text ".TID" at 1181,-1615 h60
  text "TID #:" at 774.85,-1621.82 h60
  text ".plot_File_Name" at -934.15,-1815.15 h60
  text "PLOT NAME =" at -1691.15,-1826.49 h60
  text "GENERATED    :" at 787.85,-1826.49 h60
  text ".Print_Date" at 1657.35,-1826.49 h60
  text ".Print_Time" at 2386.35,-1826.49 h60
  text "TEXAS INSTRUMENTS" at 3650.85,-1826.49 h60
M12 Stackup:
  drawing of 295 lines, arcs and shapes, not listed
  text "Layer" at 3247.58,5012 h60
  text "Name" at 3657.49,5012 h60
  text "Material" at 4597.23,5012 h60
  text "Thickness" at 5457,5012 h60
  text "Constant" at 6106.84,5012 h60
  text "Board Layer Stack" at 6676.7,5012 h60
  text "1" at 3247.58,4892 h60
  text "Top Overlay" at 3657.49,4892 h60
  text "2" at 3247.58,4772 h60
  text "Top Solder" at 3657.49,4772 h60
  text "Solder Resist" at 4597.23,4772 h60
  text "0.40mil" at 5457,4772 h60
  text "3.5" at 6106.84,4772 h60
  text "3" at 3247.58,4652 h60
  text "Top Layer" at 3657.49,4652 h60
  text "Copper" at 4597.23,4652 h60
  text "1.40mil" at 5457,4652 h60
  text "4" at 3247.58,4532 h60
  text "Dielectric1" at 3657.49,4532 h60
  text "FR-4 High Tg" at 4597.23,4532 h60
  text "4.8" at 6106.84,4532 h60
  text "5" at 3247.58,4412 h60
  text "Signal Layer 1" at 3657.49,4412 h60
  text "Copper" at 4597.23,4412 h60
  text "1.40mil" at 5457,4412 h60
  text "6" at 3247.58,4292 h60
  text "Dielectric 2" at 3657.49,4292 h60
  text "FR-4 High Tg" at 4597.23,4292 h60
  text "4.2" at 6106.84,4292 h60
  text "7" at 3247.58,4172 h60
  text "Signal Layer 2" at 3657.49,4172 h60
  text "Copper" at 4597.23,4172 h60
  text "1.40mil" at 5457,4172 h60
  text "8" at 3247.58,4052 h60
  text "Dielectric 3" at 3657.49,4052 h60
  text "FR-4 High Tg" at 4597.23,4052 h60
  text "4.2" at 6106.84,4052 h60
  text "9" at 3247.58,3932 h60
  text "Bottom Layer" at 3657.49,3932 h60
  text "Copper" at 4597.23,3932 h60
  text "1.40mil" at 5457,3932 h60
  text "10" at 3247.58,3812 h60
  text "Bottom Solder" at 3657.49,3812 h60
  text "Solder Resist" at 4597.23,3812 h60
  text "0.40mil" at 5457,3812 h60
  text "3.5" at 6106.84,3812 h60
  text "11" at 3247.58,3692 h60
  text "Bottom Overlay" at 3657.49,3692 h60
M13 Component Bodies Top:
  text ".Layer_Name" at -885.15,-1620.64 h60
M14 Component Bodies Bottom:
  text ".Layer_Name" at -885.15,-1620.64 h60
M15 Courtyards Top:
  text ".Layer_Name" at -885.15,-1620.64 h60
M16 Courtyards Bottom:
  text ".Layer_Name" at -885.15,-1620.64 h60
Drill Drawing:
  circle w10: c3686.62,2360.83 r33.33
  lines w10: 3653.29,1727.5 3719.96,1727.5 3719.96,1794.17 3653.29,1794.17 3653.29,1727.5 ; 3653.29,1944.17 3719.96,1944.17 3686.62,1877.5 3653.29,1944.17 ; 3653.29,2027.5 3653.29,2044.17 3669.96,2060.83 3653.29,2077.5 3653.29,2094.17 3669.96,2094.17 3686.62,2077.5 3703.29,2094.17 3719.96,2094.17 3719.96,2077.5 3703.29,2060.83 3719.96,2044.17 3719.96,2027.5 3703.29,2027.5 3686.62,2044.17 3669.96,2027.5 3653.29,2027.5 ; 3653.29,2194.17 3669.96,2194.17 3686.62,2177.5 3703.29,2194.17 3719.96,2194.17 3703.29,2210.83 3719.96,2227.5 3703.29,2227.5 3686.62,2244.17 3669.96,2227.5 3653.29,2227.5 3669.96,2210.83 3653.29,2194.17 ; 3653.29,2477.5 3686.62,2494.17 3719.96,2477.5 3703.29,2510.83 3719.96,2544.17 3686.62,2527.5 3653.29,2544.17 3669.96,2510.83 3653.29,2477.5
  lines w15: 3593.5,1682.5 7118.58,1682.5 ; 3593.5,2582.5 7118.58,2582.5 ; 4144.38,1532.5 4144.38,2732.5 ; 4734.22,1532.5 4734.22,2732.5 ; 5833.9,1532.5 5833.9,2732.5 ; 6339.78,1532.5 6339.78,2732.5 ; 3593.5,1532.5 7118.58,1532.5 7118.58,2732.5 3593.5,2732.5 3593.5,1532.5
  text "Symbol" at 3683.5,2627.5 h72
  text "Count" at 4189.38,2627.5 h72
  text "Hole Size" at 4779.22,2627.5 h72
  text "Plated" at 5878.9,2627.5 h72
  text "Hole Type" at 6384.78,2627.5 h72
  text "2" at 4189.38,2477.5 h60
  text "7.87mil (0.200mm)" at 4779.22,2477.5 h60
  text "PTH" at 5878.9,2477.5 h60
  text "Round" at 6384.78,2477.5 h60
  text "144" at 4189.38,2327.5 h60
  text "12.00mil (0.305mm)" at 4779.22,2327.5 h60
  text "PTH" at 5878.9,2327.5 h60
  text "Round" at 6384.78,2327.5 h60
  text "10" at 4189.38,2177.5 h60
  text "20.00mil (0.508mm)" at 4779.22,2177.5 h60
  text "PTH" at 5878.9,2177.5 h60
  text "Round" at 6384.78,2177.5 h60
  text "16" at 4189.38,2027.5 h60
  text "43.31mil (1.100mm)" at 4779.22,2027.5 h60
  text "PTH" at 5878.9,2027.5 h60
  text "Round" at 6384.78,2027.5 h60
  text "40" at 4189.38,1877.5 h60
  text "45.28mil (1.150mm)" at 4779.22,1877.5 h60
  text "PTH" at 5878.9,1877.5 h60
  text "Round" at 6384.78,1877.5 h60
  text "4" at 4189.38,1727.5 h60
  text "96.46mil (2.450mm)" at 4779.22,1727.5 h60
  text "NPTH" at 5878.9,1727.5 h60
  text "Round" at 6384.78,1727.5 h60
  text "216 Total" at 4189.38,1577.5 h60
  text "Drill Table" at 3641,1319 h60
  text "FOR 7.874MIL DRILL +0/-7.874MIL" at 3594.77,1184 h60
  text "FOR 12MIL DRILL +0/-12MIL" at 3594.77,1079 h60
  text "FOR PTH DRILL +/-3MIL" at 3590.5,992.45 h60
  text "FOR NPTH DRILL +/-2MIL" at 3594.77,909 h60
  text ".layer_Name" at -780.15,-1604.15 h60

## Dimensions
0,2559.06 to 0,0 on M2 Board Dimensions
0,0 to 1968.5,0 on M2 Board Dimensions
